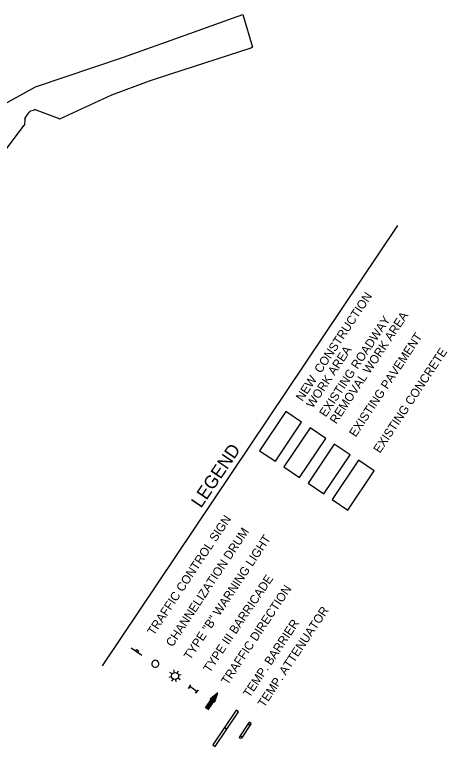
# Model space of a CAD drawing. Extents: x 1795987 to 1799689, y 243690 to 251545.
# Drawn here: x 1798473 to 1798861, y 250323 to 250979 of the extents above; entities that cross this region are included whole.
import ezdxf

# ---------------------------------------------------------------- set-up
doc = ezdxf.new("R2010")
doc.units = 0
for name, color, linetype in [('LEGEND', 7, 'Continuous'), ('Level 23', 7, 'Continuous'), ('Level 62', 7, 'Continuous')]:
    doc.layers.add(name, color=color, linetype=linetype)

# ---------------------------------------------------------------- blocks, each defined once
blk = doc.blocks.new('T21LR')
at = {"layer": 'Level 23'}
for p, q in [((0, 2), (31.5, 2)), ((0, -2), (31.5, -2))]:
    blk.add_line(p, q, dxfattribs=at)
blk.add_lwpolyline([(0, -2), (4, -2), (4, 2), (0, 2)], close=True, dxfattribs=at)
blk.add_circle((31.5, 0), 2, dxfattribs=at)

msp = doc.modelspace()

# ---------------------------------------------------------------- linework, layer by layer
at = {"layer": 'LEGEND'}
for p, q in [((1798551.69, 250395.05), (1798817.07, 250790.3)), ((1798587.01, 250404.22), (1798577.3, 250410.74)), ((1798614.18, 250387.64), (1798612.27, 250388.93)), ((1798616.22, 250389), (1798615.77, 250391.27)), ((1798618.62, 250388.52), (1798619.9, 250390.43)), ((1798622.24, 250386.93), (1798619.97, 250386.48)), ((1798611.43, 250384.8), (1798613.7, 250385.25)), ((1798615.06, 250383.21), (1798613.77, 250381.29)), ((1798617.9, 250380.46), (1798617.45, 250382.73)), ((1798619.49, 250384.08), (1798621.41, 250382.79)), ((1798655.26, 250370.85), (1798648.28, 250365.16)), ((1798652.4, 250362.31), (1798655.26, 250370.85)), ((1798649.05, 250364.62), (1798643.89, 250357.15)), ((1798646.46, 250355.37), (1798651.62, 250362.85)), ((1798648.28, 250365.16), (1798649.05, 250364.62)), ((1798651.62, 250362.85), (1798652.4, 250362.31))]:
    msp.add_line(p, q, dxfattribs=at)
for points in [[(1798706.99, 250578.57), (1798730.56, 250613.67), (1798716.38, 250623.19), (1798692.82, 250588.09)], [(1798728.71, 250563.99), (1798752.28, 250599.09), (1798738.11, 250608.6), (1798714.54, 250573.51)], [(1798750.44, 250549.41), (1798774, 250584.5), (1798759.83, 250594.02), (1798736.26, 250558.92)], [(1798772.16, 250534.82), (1798795.72, 250569.92), (1798781.55, 250579.43), (1798757.99, 250544.34)], [(1798581.34, 250408.03), (1798582.43, 250409.65), (1798584.05, 250408.56), (1798582.96, 250406.94)], [(1798673.72, 250353.82), (1798671.64, 250355.21), (1798661.19, 250339.65), (1798663.27, 250338.25)], [(1798663.27, 250338.25), (1798661.19, 250339.65), (1798650.74, 250324.08), (1798652.82, 250322.68)]]:
    msp.add_lwpolyline(points, close=True, dxfattribs=at)
for points in [[(1798637.47, 250373.52), (1798635.24, 250370.32), (1798636.36, 250371.92), (1798629.95, 250376.37), (1798628.84, 250374.77), (1798631.07, 250377.97)], [(1798651.36, 250367.67), (1798644.03, 250357.05)], [(1798652.09, 250368.26), (1798644.24, 250356.91)], [(1798652.81, 250368.86), (1798644.46, 250356.76)], [(1798653.54, 250369.45), (1798644.67, 250356.61)], [(1798654.26, 250370.04), (1798644.88, 250356.46)], [(1798654.98, 250370.63), (1798645.1, 250356.32)], [(1798655.07, 250370.3), (1798645.31, 250356.17)], [(1798654.77, 250369.41), (1798645.52, 250356.02)], [(1798654.48, 250368.52), (1798645.74, 250355.87)], [(1798654.18, 250367.64), (1798645.95, 250355.73)], [(1798653.88, 250366.75), (1798646.17, 250355.58)], [(1798653.59, 250365.86), (1798646.38, 250355.43)], [(1798648.46, 250365.31), (1798648.33, 250365.12)], [(1798649.19, 250365.9), (1798648.55, 250364.97)], [(1798649.91, 250366.49), (1798648.76, 250364.82)], [(1798650.64, 250367.08), (1798648.98, 250364.68)], [(1798653.29, 250364.97), (1798651.76, 250362.75)], [(1798652.99, 250364.09), (1798651.97, 250362.61)], [(1798652.69, 250363.2), (1798652.18, 250362.46)]]:
    msp.add_lwpolyline(points, dxfattribs=at)
msp.add_circle((1798616.84, 250385.86), 3.19, dxfattribs=at)
for start, end in [(56.12215, 236.12215), (236.12215, 56.12215)]:
    msp.add_arc((1798599.13, 250396.78), 3.18, start, end, dxfattribs=at)
at = {"layer": 'Level 62'}
for p, q in [((1798668.45, 250976.22), (1798677.83, 250979.45)), ((1798668.45, 250976.22), (1798677.83, 250979.45)), ((1798677.83, 250979.45), (1798686.34, 250950.23)), ((1798677.83, 250979.45), (1798686.34, 250950.23)), ((1798630, 250962.47), (1798668.45, 250976.22)), ((1798630, 250962.47), (1798668.45, 250976.22)), ((1798570.52, 250941.2), (1798630, 250962.47)), ((1798570.52, 250941.2), (1798630, 250962.47)), ((1798491.32, 250914.63), (1798570.52, 250941.2)), ((1798491.32, 250914.63), (1798570.52, 250941.2)), ((1798612.69, 250926), (1798593.64, 250919.71)), ((1798612.69, 250926), (1798593.64, 250919.71)), ((1798593.64, 250919.71), (1798559.85, 250907.31)), ((1798593.64, 250919.71), (1798559.85, 250907.31)), ((1798431.57, 250881.49), (1798491.32, 250914.63)), ((1798431.57, 250881.49), (1798491.32, 250914.63)), ((1798559.85, 250907.31), (1798513, 250885.53)), ((1798559.85, 250907.31), (1798513, 250885.53)), ((1798489.61, 250893.48), (1798487.03, 250892.83)), ((1798489.61, 250893.48), (1798487.03, 250892.83)), ((1798490.6, 250894.25), (1798489.61, 250893.48)), ((1798490.6, 250894.25), (1798489.61, 250893.48)), ((1798512, 250886.32), (1798490.6, 250894.25)), ((1798512, 250886.32), (1798490.6, 250894.25)), ((1798513, 250885.53), (1798512, 250886.32)), ((1798513, 250885.53), (1798512, 250886.32)), ((1798480.51, 250879.39), (1798464.83, 250858.78)), ((1798480.51, 250879.39), (1798464.83, 250858.78)), ((1798481.52, 250880.29), (1798480.51, 250879.39)), ((1798481.52, 250880.29), (1798480.51, 250879.39))]:
    msp.add_line(p, q, dxfattribs=at)
for points in [[(1798686.34, 250950.23), (1798685.01, 250949.46), (1798612.69, 250926)], [(1798686.34, 250950.23), (1798685.01, 250949.46), (1798612.69, 250926)], [(1798487.03, 250892.83), (1798486.29, 250892.47), (1798485.52, 250891.59)], [(1798487.03, 250892.83), (1798486.29, 250892.47), (1798485.52, 250891.59)], [(1798485.52, 250891.59), (1798483.88, 250889.72), (1798481.58, 250885.86)], [(1798485.52, 250891.59), (1798483.88, 250889.72), (1798481.58, 250885.86)], [(1798481.58, 250885.86), (1798481.89, 250885.49), (1798481.52, 250880.29)], [(1798481.58, 250885.86), (1798481.89, 250885.49), (1798481.52, 250880.29)], [(1798736.26, 250558.92), (1798750.44, 250549.41), (1798774, 250584.5), (1798759.83, 250594.02), (1798736.26, 250558.92)]]:
    msp.add_lwpolyline(points, dxfattribs=at)

# ---------------------------------------------------------------- block references
at = {"layer": 'LEGEND', "xscale": 0.5000000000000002, "yscale": 0.5000000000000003, "rotation": -123.72854882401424}
msp.add_blockref('T21LR', (1798684.34, 250343.84), dxfattribs=at)

# ---------------------------------------------------------------- texts
at = {"layer": 'LEGEND'}
for s, height, rotation, p in [('NEW  CONSTRUCTION', 7.7999, 56.43516, (1798731.16, 250631.88)), ('EXISTING ROADWAY', 7.7999, 56.43516, (1798752.25, 250617.72)), ('REMOVAL WORK AREA', 7.7999, 56.43516, (1798761.62, 250611.5)), ('EXISTING PAVEMENT', 7.7999, 56.43516, (1798779.07, 250599.73)), ('WORK AREA', 7.8, 56.43516, (1798740.52, 250625.66)), ('EXISTING CONCRETE', 7.7999, 56.43516, (1798800.83, 250585.21)), ('LEGEND', 11.7, 55.95613, (1798640.14, 250535.91)), ('TRAFFIC CONTROL SIGN', 7.7999, 56.43516, (1798597.78, 250421.64)), ('CHANNELIZATION DRUM', 7.7999, 56.43516, (1798614.45, 250411.34)), ('TYPE "B" WARNING LIGHT', 7.7999, 56.43516, (1798630.52, 250399.65)), ('TYPE III BARRICADE', 7.7999, 55.95613, (1798648, 250388.28)), ('TRAFFIC DIRECTION', 7.7999, 56.43516, (1798664.08, 250377.29)), ('TEMP. ATTENUATOR', 7.7999, 56.43516, (1798696.96, 250357.06)), ('TEMP. BARRIER', 7.7999, 56.43516, (1798683.78, 250365.84))]:
    msp.add_text(s, height=height, rotation=rotation, dxfattribs=at).set_placement(p)

doc.saveas('drawing.dxf')
